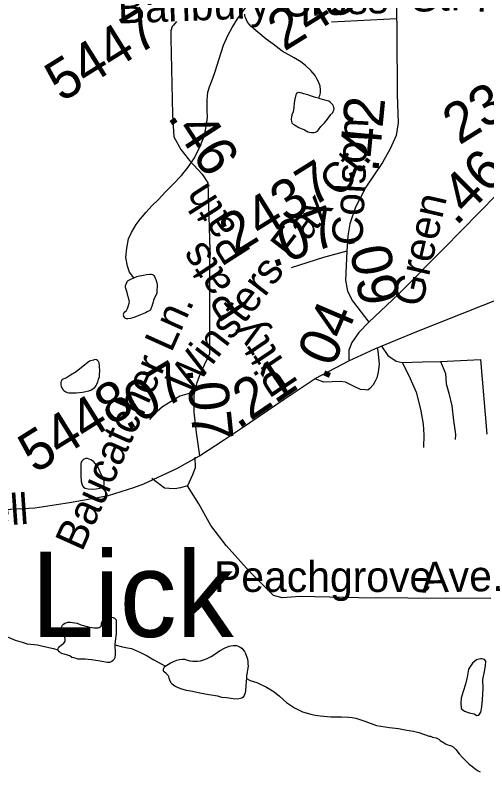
# Model space of a CAD drawing. Extents: x 2001466 to 31450019, y -30647475 to 847247.
# Drawn here: x 2186797 to 2189729, y 751202 to 755901 of the extents above; entities that cross this region are included whole.
import ezdxf

# ---------------------------------------------------------------- set-up
doc = ezdxf.new("R2010")
doc.units = 0
for name, color, linetype in [('Exist Civil Demographics Community Label', 7, 'Continuous'), ('Exist Hydrographic Misc Water Feature', 7, 'Continuous'), ('Exist Road Non-System Type 51', 7, 'Continuous'), ('Exist Road Non-System Type 51 Label', 7, 'Continuous'), ('Exist Road Primary NC Attributed', 7, 'Continuous'), ('Exist Road Primary NC Label', 7, 'Continuous'), ('Exist Road Primary NC Service Mileage Hundredths English Label', 7, 'Continuous'), ('Exist Road Secondary Mileage Hundredths English Label', 7, 'Continuous'), ('Exist Road Secondary Type 51 Attributed', 7, 'Continuous'), ('Exist Road Secondary Type 51 Label', 7, 'Continuous'), ('Exist Road Secondary Type 51 Number Label', 7, 'Continuous')]:
    doc.layers.add(name, color=color, linetype=linetype)

msp = doc.modelspace()

# ---------------------------------------------------------------- linework, layer by layer
at = {"layer": 'Exist Hydrographic Misc Water Feature'}
for points in [[(2187534.2, 754269.1), (2187507.7, 754304.7), (2187495.8, 754342.6), (2187485.2, 754396.6), (2187491.1, 754454.5), (2187502.4, 754512.8), (2187520.2, 754550.7), (2187549.8, 754601), (2187574, 754633), (2187611.5, 754677.3), (2187647, 754717.3), (2187688.6, 754755.7), (2187732.5, 754804.2), (2187778, 754848.4), (2187831.7, 754904.8), (2187873.1, 754957), (2187911.3, 755015.3), (2187948.6, 755091.6), (2187974, 755155.5), (2187987.5, 755221.6), (2187993.3, 755265.8), (2187990.6, 755311.6), (2187990.4, 755373.7), (2187995.7, 755423.6), (2188005.8, 755455.8), (2188023.6, 755503.8), (2188041.3, 755551.8), (2188064.6, 755630.2), (2188091.7, 755714.1), (2188119.2, 755774.5), (2188145.4, 755824.5), (2188179.3, 755877), (2188228.7, 755947)], [(2188681.9, 755384.4), (2188690.1, 755402.6), (2188695.6, 755418.4), (2188695.8, 755436.7), (2188693.3, 755460.6), (2188685.5, 755482.4), (2188673.2, 755506.2), (2188660.9, 755526.3), (2188634.9, 755556.2), (2188602.7, 755587.8), (2188572.8, 755611.4), (2188530.3, 755635.3), (2188456.1, 755676.9), (2188400.1, 755720.3), (2188357.7, 755752.2), (2188305.6, 755795.8), (2188263.1, 755829.4), (2188250.8, 755845.5), (2188241, 755857.1), (2188235.2, 755871.3), (2188228.7, 755885.3), (2188224.8, 755895.2), (2188224.6, 755907)], [(2188681.9, 755384.4), (2188663.8, 755390.4), (2188640, 755398), (2188615.8, 755406.1), (2188592.2, 755411.8), (2188571.9, 755417.7), (2188565.8, 755419.8), (2188559.8, 755419.5), (2188556.2, 755419.7), (2188550.2, 755417.3), (2188545.7, 755413.5), (2188541.8, 755405.6), (2188536.3, 755379.3), (2188530.3, 755357.4), (2188528.3, 755327.3), (2188525, 755301.5), (2188517, 755281.6), (2188514.9, 755267.3), (2188512.9, 755259.5), (2188513.1, 755253.3), (2188515.3, 755241.2), (2188517.4, 755233.2), (2188521.5, 755227.3), (2188525.2, 755223.5), (2188533.4, 755219.4), (2188561.3, 755203.8), (2188595.7, 755188.1), (2188615.4, 755176.2), (2188623.6, 755174.2), (2188639.4, 755172.2), (2188653.6, 755172.5), (2188663.6, 755174.2), (2188675.7, 755180.5), (2188683.3, 755188.7), (2188697.2, 755208.5), (2188719.2, 755232.8), (2188739.1, 755254.9), (2188758.5, 755283.2), (2188770.6, 755297.1), (2188774.5, 755303), (2188778.4, 755311), (2188780.7, 755321.2), (2188778.2, 755327.2), (2188776.6, 755335.2), (2188772.5, 755343.1), (2188764.3, 755352.9), (2188756.3, 755359), (2188746.2, 755367), (2188722, 755372.7), (2188693.9, 755380.6), (2188681.9, 755384.4)], [(2187534.2, 754269.1), (2187554.1, 754277), (2187570.1, 754281.1), (2187584, 754285.1), (2187595.9, 754285.3), (2187613.9, 754289.5), (2187633.8, 754291.7), (2187642, 754291.7), (2187650.2, 754289.7), (2187654.1, 754287.9), (2187659.9, 754283.8), (2187664, 754277.9), (2187668.3, 754267.9), (2187672, 754260), (2187678.1, 754238), (2187680.4, 754225.9), (2187680.4, 754213.7), (2187678.9, 754194.1), (2187676.9, 754174.1), (2187674.6, 754163.9), (2187660.9, 754142), (2187657, 754129.6), (2187655, 754119.8), (2187647.4, 754091.7), (2187643.5, 754083.8), (2187641.2, 754077.7), (2187637.7, 754071.7), (2187633.6, 754067.5), (2187625.4, 754061.8), (2187617.4, 754057.7), (2187608, 754051.5), (2187575.8, 754039.3), (2187542, 754025), (2187528, 754021), (2187513.9, 754017), (2187497.7, 754014.6), (2187494, 754014.8), (2187490.1, 754014.5), (2187486.2, 754016.7), (2187481.9, 754016.5), (2187478, 754020.8), (2187473.9, 754026.7), (2187471.4, 754030.7), (2187471.6, 754036.4), (2187471.8, 754040.4), (2187471.6, 754044.5), (2187471.4, 754048.5), (2187473.9, 754052.6), (2187479.6, 754058.7), (2187489.3, 754066.5), (2187495.6, 754078.6), (2187499.7, 754092.6), (2187505.1, 754112.8), (2187507.3, 754120.6), (2187505.1, 754130.7), (2187499.1, 754152.7), (2187492.8, 754178.8), (2187484.8, 754202.7), (2187482.5, 754214.4), (2187482.5, 754222.5), (2187486.4, 754230.5), (2187490.7, 754240.4), (2187494.2, 754246.7), (2187499.9, 754252.8), (2187516.1, 754260.9), (2187534.2, 754269.1)], [(2187176.2, 753686.7), (2187142.3, 753664.3), (2187116.7, 753648.2), (2187096.6, 753639.9), (2187088.8, 753635.9), (2187084.7, 753632), (2187082.7, 753627.8), (2187081, 753620), (2187080.8, 753613.9), (2187080.8, 753604.2), (2187082.9, 753596.1), (2187086.8, 753585.8), (2187093.1, 753575.9), (2187099.5, 753570.1), (2187111.4, 753562.3), (2187121.2, 753558.3), (2187131.2, 753556.4), (2187153.4, 753554.7), (2187177.2, 753554.7), (2187215.3, 753559.1), (2187255.3, 753567.3), (2187267, 753571.2), (2187282.8, 753581.4), (2187293, 753589.5), (2187301, 753601.3), (2187304.9, 753609.7), (2187310.7, 753623.4), (2187316.2, 753639.6), (2187320.7, 753655.6), (2187322.4, 753671.5), (2187324.2, 753689.5), (2187321.7, 753723.5), (2187320.1, 753741.6), (2187315.8, 753749.6), (2187309.6, 753755.4), (2187303.5, 753759.6), (2187293.6, 753761.5), (2187284, 753759.3), (2187276, 753757.3), (2187259.6, 753751.2), (2187250.2, 753745.3), (2187176.2, 753686.7)], [(2187204.7, 753041.1), (2187206.7, 753005.1), (2187210.8, 752991.1), (2187215.3, 752977), (2187221.3, 752969.2), (2187233, 752963.3), (2187251, 752959.5), (2187277, 752957.5), (2187301.2, 752960), (2187323.2, 752964), (2187341.2, 752970.2), (2187347.4, 752976.1), (2187351.3, 752984.1), (2187351.1, 752996.3), (2187351.1, 753006), (2187344.7, 753024), (2187326.3, 753062), (2187312.5, 753091.7), (2187302.3, 753105.9), (2187292.2, 753119.5), (2187286.3, 753127.7), (2187277.9, 753133.4), (2187267.8, 753139.4), (2187258, 753143.4), (2187247.9, 753147.3), (2187236, 753147.1), (2187226, 753143.3), (2187220.2, 753138.9), (2187212, 753131.2), (2187208.1, 753124.9), (2187206.5, 753115), (2187206.1, 753102.9), (2187204.7, 753041.1)], [(2186493.1, 752184.4), (2186542.7, 752166.7), (2186563.3, 752158.8), (2186585, 752147), (2186613.5, 752129.2), (2186641.2, 752109.7), (2186675.6, 752085.8), (2186703.7, 752063.7), (2186740, 752044), (2186798.2, 752018.6), (2186840.1, 752006.6), (2186871.9, 751996.9), (2186936.2, 751989.7), (2186970.1, 751981.7), (2187036.3, 751968.4), (2187062.1, 751960.4)], [(2187062.1, 751960.4), (2187061.9, 751964.5), (2187066.2, 751972.4), (2187074, 751980.6), (2187083.9, 751988.4), (2187099.9, 752000.6), (2187104, 752006.9), (2187107.9, 752012.8), (2187107.7, 752018.9), (2187107.7, 752026.6), (2187105.4, 752036.7), (2187103.8, 752046.7), (2187095.4, 752062.6), (2187085.5, 752080.7), (2187085.5, 752088.3), (2187085.3, 752096.5), (2187087, 752104.4), (2187091.5, 752112.6), (2187097, 752118.7), (2187105.2, 752124.7), (2187115, 752126.9), (2187124.9, 752130.7), (2187139, 752131), (2187154.8, 752129), (2187169, 752127.2), (2187183.1, 752125.1), (2187205.3, 752115.3), (2187245.5, 752103.6), (2187261.3, 752099.5), (2187273.3, 752097.7), (2187289.1, 752095.7), (2187305.3, 752096.1), (2187312.9, 752096.2), (2187319.3, 752098.1), (2187325, 752102.1), (2187331.4, 752106.4), (2187333, 752112.2), (2187334.7, 752122.1), (2187338.8, 752136.1), (2187342.7, 752144.4), (2187346.6, 752152.4), (2187354.8, 752158.4), (2187362.8, 752160.5), (2187374.6, 752162.3), (2187394.5, 752162.5), (2187406.6, 752160.7), (2187414.4, 752156.7), (2187420.8, 752150.9), (2187424.9, 752145), (2187425.1, 752138.9), (2187424.9, 752114.9), (2187425.3, 752058.9), (2187419.8, 752012.7), (2187415.9, 751991)], [(2187415.9, 751991), (2187418.1, 751940.8), (2187418.7, 751926.9), (2187416.7, 751917), (2187416.5, 751908.9), (2187414.6, 751904.8), (2187412.2, 751901.1), (2187408.5, 751896.8), (2187406.2, 751893), (2187398.8, 751886.9), (2187390.6, 751882.8), (2187384.7, 751880.5), (2187378.7, 751880.6), (2187368.9, 751880.5), (2187358.7, 751882.4), (2187324.8, 751888.3), (2187272.7, 751897.8), (2187251, 751899.9), (2187232.5, 751901.4), (2187196.9, 751901.2), (2187186.6, 751901.1), (2187176.6, 751905), (2187162.4, 751909.2), (2187150.5, 751911), (2187136.4, 751922.9), (2187116.5, 751928.8), (2187094.3, 751934.5), (2187086.8, 751936.5), (2187082.4, 751938.8), (2187078.3, 751940.5), (2187072.2, 751946.4), (2187062.1, 751960.4)], [(2187415.9, 751991), (2187464, 751977.2), (2187496.2, 751971.5), (2187520.2, 751967.5), (2187576.2, 751944), (2187618, 751922.3), (2187658.4, 751896.7), (2187708.5, 751870.9), (2187730.8, 751859)], [(2187730.8, 751859), (2187740.7, 751865.2), (2187760.6, 751877.2), (2187780.6, 751887.6), (2187802.4, 751895.6), (2187818.4, 751899.7), (2187834.4, 751901.8), (2187850.6, 751901.8), (2187862.7, 751897.9), (2187882.6, 751892.1), (2187902.2, 751888.3), (2187916.2, 751888.2), (2187930.7, 751888.4), (2187948.6, 751890.6), (2187968.7, 751896.5), (2187990, 751905), (2188016.3, 751918.9), (2188038, 751933.1), (2188067.7, 751953.3), (2188101.8, 751971.7), (2188127.8, 751981.6), (2188137.4, 751983.8), (2188151.8, 751986.1), (2188161.6, 751986.2), (2188173.5, 751986), (2188184, 751982), (2188195.7, 751976.2), (2188205.7, 751970.2), (2188213.9, 751960.4), (2188222.1, 751948.2), (2188229.9, 751936.5), (2188238.1, 751914.6), (2188242.2, 751900.6), (2188244.1, 751886.5), (2188244.3, 751872.7), (2188244.5, 751858.5), (2188241, 751834.6), (2188238.7, 751818.4), (2188234.8, 751800.7), (2188234.8, 751782.5)], [(2189704.9, 751718.9), (2189704.2, 751774.6), (2189714.5, 751825), (2189720, 751860.6), (2189721.7, 751888.8), (2189713.5, 751898.9), (2189699.7, 751902.7), (2189689.9, 751904.6), (2189663.6, 751898.4), (2189639.6, 751876.4), (2189614, 751840.1), (2189606.6, 751790.1), (2189596.8, 751746.2), (2189581.4, 751699.9), (2189569.7, 751659.8), (2189567.7, 751629.7), (2189569.9, 751595.7), (2189590, 751578.1), (2189619.8, 751568.3), (2189649.9, 751562.5), (2189666.1, 751552.4), (2189678.4, 751554.6), (2189691.9, 751572.8), (2189697.7, 751604.8), (2189701.2, 751648.9), (2189704.9, 751718.9)], [(2188234.8, 751782.5), (2188233, 751764.5), (2188231.4, 751736.7), (2188227.9, 751704.4), (2188225.6, 751686.5), (2188219.5, 751672.4), (2188213.7, 751666.3), (2188205.9, 751660.2), (2188197.9, 751658.2), (2188179.9, 751654), (2188152.2, 751656.2), (2188110.2, 751661.7), (2188082.1, 751663.6), (2188056, 751671.5), (2188000.1, 751679.2), (2187945.9, 751690.6), (2187899.8, 751700.4), (2187861.6, 751707.8), (2187827.6, 751717.8), (2187801.6, 751727.4), (2187789.3, 751733.3), (2187781.5, 751739.4), (2187773.5, 751745.5), (2187767.5, 751753.3), (2187759.1, 751771.2), (2187755.2, 751783.1), (2187753.2, 751791.2), (2187749.3, 751799.4), (2187742.9, 751807.3), (2187735.1, 751813), (2187723, 751822.8), (2187719.1, 751827.1), (2187718.7, 751834.9), (2187718.9, 751840.9), (2187722.6, 751850.9), (2187726.7, 751855.1), (2187730.8, 751859)], [(2188234.8, 751782.5), (2188257.2, 751768.9), (2188299.4, 751756.9), (2188359.5, 751727.5), (2188407.3, 751698), (2188439.5, 751672), (2188484, 751632.5), (2188534.4, 751598.5), (2188582.4, 751575), (2188634.5, 751559.4), (2188662.4, 751553.5), (2188692.5, 751549.8), (2188758.7, 751544.3), (2188826.4, 751542.5), (2188870.3, 751541.2), (2188892.4, 751539.1), (2188914.4, 751535.4), (2188944.7, 751525.5), (2188970.8, 751515.9), (2189042.9, 751490.4), (2189123.1, 751476.6), (2189178.7, 751471.1), (2189231, 751461.5), (2189273.2, 751454), (2189305, 751445.9), (2189371.2, 751422.5)], [(2189371.2, 751422.5), (2189379.2, 751422.5), (2189391.1, 751416.7), (2189413.3, 751412.9), (2189429.5, 751404.8), (2189439.1, 751396.8), (2189463.3, 751381.4), (2189475.6, 751373.1), (2189485.7, 751369.5), (2189503.7, 751365.6), (2189511.5, 751361.6), (2189519.3, 751357.5), (2189535.7, 751341.6), (2189557.6, 751314), (2189578.1, 751291.9), (2189596, 751272.1), (2189618.3, 751250.5), (2189642.5, 751232.6), (2189656.3, 751220.8), (2189674.7, 751208.7), (2189688.2, 751201)]]:
    msp.add_lwpolyline(points, dxfattribs=at)
at = {"layer": 'Exist Road Non-System Type 51'}
msp.add_line((2189167.2, 755877.8), (2188763.1, 755858.2), dxfattribs=at)
for points in [[(2189046.1, 753835), (2189052.1, 753813.6), (2189060, 753734.6), (2189054.1, 753683.2), (2189044.2, 753649.6), (2189034.3, 753627.9), (2189022.5, 753606.2), (2189000.8, 753582.5), (2188988.9, 753572.6), (2188975.1, 753574.6), (2188943.5, 753576.6), (2188904, 753594.3), (2188850.7, 753622), (2188819.2, 753625.9), (2188716.5, 753622), (2188659.4, 753643.2)], [(2189073.9, 753846.3), (2189113.3, 753787.9), (2189164.6, 753752.4), (2189203.4, 753744.6)], [(2189441.4, 753749.7), (2189689.6, 753762.6), (2189728.1, 753297.9)], [(2189203.4, 753744.6), (2189329.4, 753748), (2189441.4, 753749.7)], [(2189203.4, 753744.6), (2189243.7, 753663.8), (2189289.5, 753558.9), (2189315.4, 753454.4), (2189333.4, 753360), (2189338.1, 753293.9), (2189334.5, 753216)], [(2189441.4, 753749.7), (2189472.6, 753675.3), (2189476.5, 753612.1), (2189492.3, 753552.9), (2189512, 753473.8), (2189521.9, 753383), (2189534.1, 753295.9), (2189531.5, 753266)], [(2187914.2, 753156.4), (2187915.5, 753088.8), (2187899.4, 753045.6), (2187868.8, 752977.3)], [(2187868.8, 752977.3), (2187825.7, 752964.7), (2187789.7, 752959.3), (2187755.5, 752961.1), (2187725, 752962.9), (2187647.4, 753024.1)], [(2189754, 752278), (2189237.9, 752281.4), (2188932.3, 752283.2), (2188569.2, 752290.4), (2188455.9, 752283.2), (2188402, 752297.6), (2188253.5, 752446.6), (2188107.9, 752606.7), (2188014.4, 752730.8), (2187938.9, 752865.7), (2187868.8, 752977.3)]]:
    msp.add_lwpolyline(points, dxfattribs=at)
at = {"layer": 'Exist Road Primary NC Attributed'}
for points in [[(2188870.3, 753753.2), (2189033, 753829.7), (2189293.6, 753935.4), (2189576.1, 754048.5), (2189956.5, 754199.3), (2190436.2, 754388.8), (2190737.1, 754504), (2190941.1, 754567.9), (2191258.7, 754637), (2191365.4, 754655.8)], [(2187943.5, 753164.5), (2188099.2, 753265.6), (2188204.9, 753335.8), (2188470.1, 753516.1), (2188661.6, 753644.3), (2188870.3, 753753.2)], [(2185310, 752739.6), (2185472.7, 752749), (2185673.6, 752764.7), (2186042.5, 752793), (2186420.2, 752813.9), (2186918.8, 752841.2), (2187134.4, 752873.6), (2187376.6, 752918.7), (2187535.3, 752968.3), (2187597.7, 752990.1), (2187802, 753086.1), (2187943.5, 753164.5), (2187940.8, 753162.7)]]:
    msp.add_lwpolyline(points, dxfattribs=at)
at = {"layer": 'Exist Road Secondary Type 51 Attributed'}
for points in [[(2189413.1, 756503.5), (2189333.6, 756378.9), (2189209.6, 756236.5), (2189180.3, 756175.7), (2189164.6, 756088.8), (2189168.3, 755791.5), (2189171.9, 755408.2), (2189178.2, 755232.3), (2189165.7, 755153.8), (2189128.5, 755070), (2189079.3, 754986.2), (2188976.8, 754833.3), (2188912.4, 754708.7), (2188876.9, 754605.1), (2188865.3, 754530.7), (2188858, 754434.4)], [(2187800.7, 755861.6), (2187781.2, 755838.9), (2187773.6, 755830.7), (2187765.5, 755804.1), (2187765.5, 755757.6), (2187774.8, 755281.2), (2187783, 755144.9), (2187826.5, 755065.9), (2187881, 754997.7), (2187960, 754913.3), (2187995.4, 754858.8), (2188007.7, 754441.8), (2188004.9, 754335.5), (2188004.9, 754172), (2188004.9, 753798.7), (2187972.3, 753726.4), (2187946.4, 753673.3), (2187925.9, 753617.4), (2187907.3, 753545.7)], [(2190653.1, 755642.8), (2190203.1, 755193.5), (2189899.7, 754898.3), (2189461.3, 754452.2), (2189178.7, 754167.4), (2188996.1, 753993.5)], [(2188858, 754434.4), (2188714.1, 754395.6), (2188513.2, 754331.8)], [(2188858, 754434.4), (2188851.2, 754254.3), (2188862.7, 754187.3), (2188894.1, 754126.5), (2188996.1, 753993.5)], [(2188996.1, 753993.5), (2188932.3, 753929.7), (2188889.4, 753867.9), (2188870.6, 753819.7), (2188870.3, 753753.2)], [(2187907.3, 753545.7), (2187879.3, 753550.4), (2187821.5, 753534.8), (2187712.4, 753469.2), (2187662.1, 753423.7), (2187633.3, 753389.6)], [(2187907.3, 753545.7), (2187908.3, 753434.5), (2187921.4, 753308.5), (2187943.5, 753164.5)]]:
    msp.add_lwpolyline(points, dxfattribs=at)

# ---------------------------------------------------------------- texts
at = {"layer": 'Exist Civil Demographics Community Label'}
msp.add_text('Lizard Lick', height=530, dxfattribs=at).set_placement((2184767.7, 752039.6))
at = {"layer": 'Exist Road Non-System Type 51 Label'}
for s, rotation, p in [('Banbury Cross  St.', 2.2733, (2187438.9, 755848.2)), ('Ave.', 1.3833, (2189324.6, 752314.1))]:
    msp.add_text(s, height=190, rotation=rotation, dxfattribs=at).set_placement(p)
msp.add_text('Peachgrove', height=190, dxfattribs=at).set_placement((2188033.3, 752319.2))
at = {"layer": 'Exist Road Primary NC Label'}
msp.add_text('Wendell', height=190, rotation=4.0239, dxfattribs=at).set_placement((2185970.3, 752678.1))
at = {"layer": 'Exist Road Primary NC Service Mileage Hundredths English Label'}
msp.add_text('.21', height=250, rotation=34.2066, dxfattribs=at).set_placement((2188182.2, 753326.6))
at = {"layer": 'Exist Road Secondary Mileage Hundredths English Label'}
for s, rotation, p in [('.42', 84.5332, (2189053.7, 754919.9)), ('.46', 303.0098, (2187740, 755270.2)), ('.46', 45.1477, (2189538, 754586.4)), ('.07', 20.4498, (2188394.8, 754330.5)), ('.09', 281.3053, (2188857.1, 754538.1)), ('.04', 66.8099, (2188735.4, 753621.2)), ('.07', 30.977, (2187490.4, 753314.3)), ('.07', 275.9044, (2187859.6, 753707.2))]:
    msp.add_text(s, height=250, rotation=rotation, dxfattribs=at).set_placement(p)
at = {"layer": 'Exist Road Secondary Type 51 Label'}
for s, rotation, p in [('Perry', 356.8108, (2189663.4, 755924.2)), ('Colson', 87.1736, (2188954, 754467.6)), ('Winsters Fax Ct.', 52.3678, (2187873.9, 753530.6)), ('Path', 122.6295, (2188268.5, 754432.9)), ('Green', 77.0658, (2189323.9, 754080.9)), ('Pitty Pats', 123.8832, (2188561.4, 753618.1)), ('Baucatcher Ln.', 65.8315, (2187213.1, 752563.5))]:
    msp.add_text(s, height=190, rotation=rotation, dxfattribs=at).set_placement(p)
at = {"layer": 'Exist Road Secondary Type 51 Number Label'}
for s, p in [('2436', (2188469.5, 755673)), ('5447', (2187086.1, 755356.6)), ('2368', (2189557.1, 755090.6)), ('2437', (2188168.9, 754409.5)), ('5448', (2186920.4, 753050.8))]:
    msp.add_text(s, height=250, rotation=31.918, dxfattribs=at).set_placement(p)

doc.saveas('drawing.dxf')
